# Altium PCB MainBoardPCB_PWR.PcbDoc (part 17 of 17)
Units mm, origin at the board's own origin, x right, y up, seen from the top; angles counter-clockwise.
Board outline 333.63 x 349.38 mm, 16 copper layers (L1, L2 (GND), L3 (Sign), L4 (GND), L5 (Sign), L6 (PWR/GND), L7(PWR/GND), L8 (PWR/GND), L9 (PWR/GND), L10 (PWR/GND), L11 (PWR/GND), L12 (Sign), L13 (GND), L14 (Sign), L15 (GND), L16), stack 2.503 mm thick; 2187 components, 1615 nets, 7987 pads, 1695 vias.
Unrouted connection lines stored in the file: 4757.
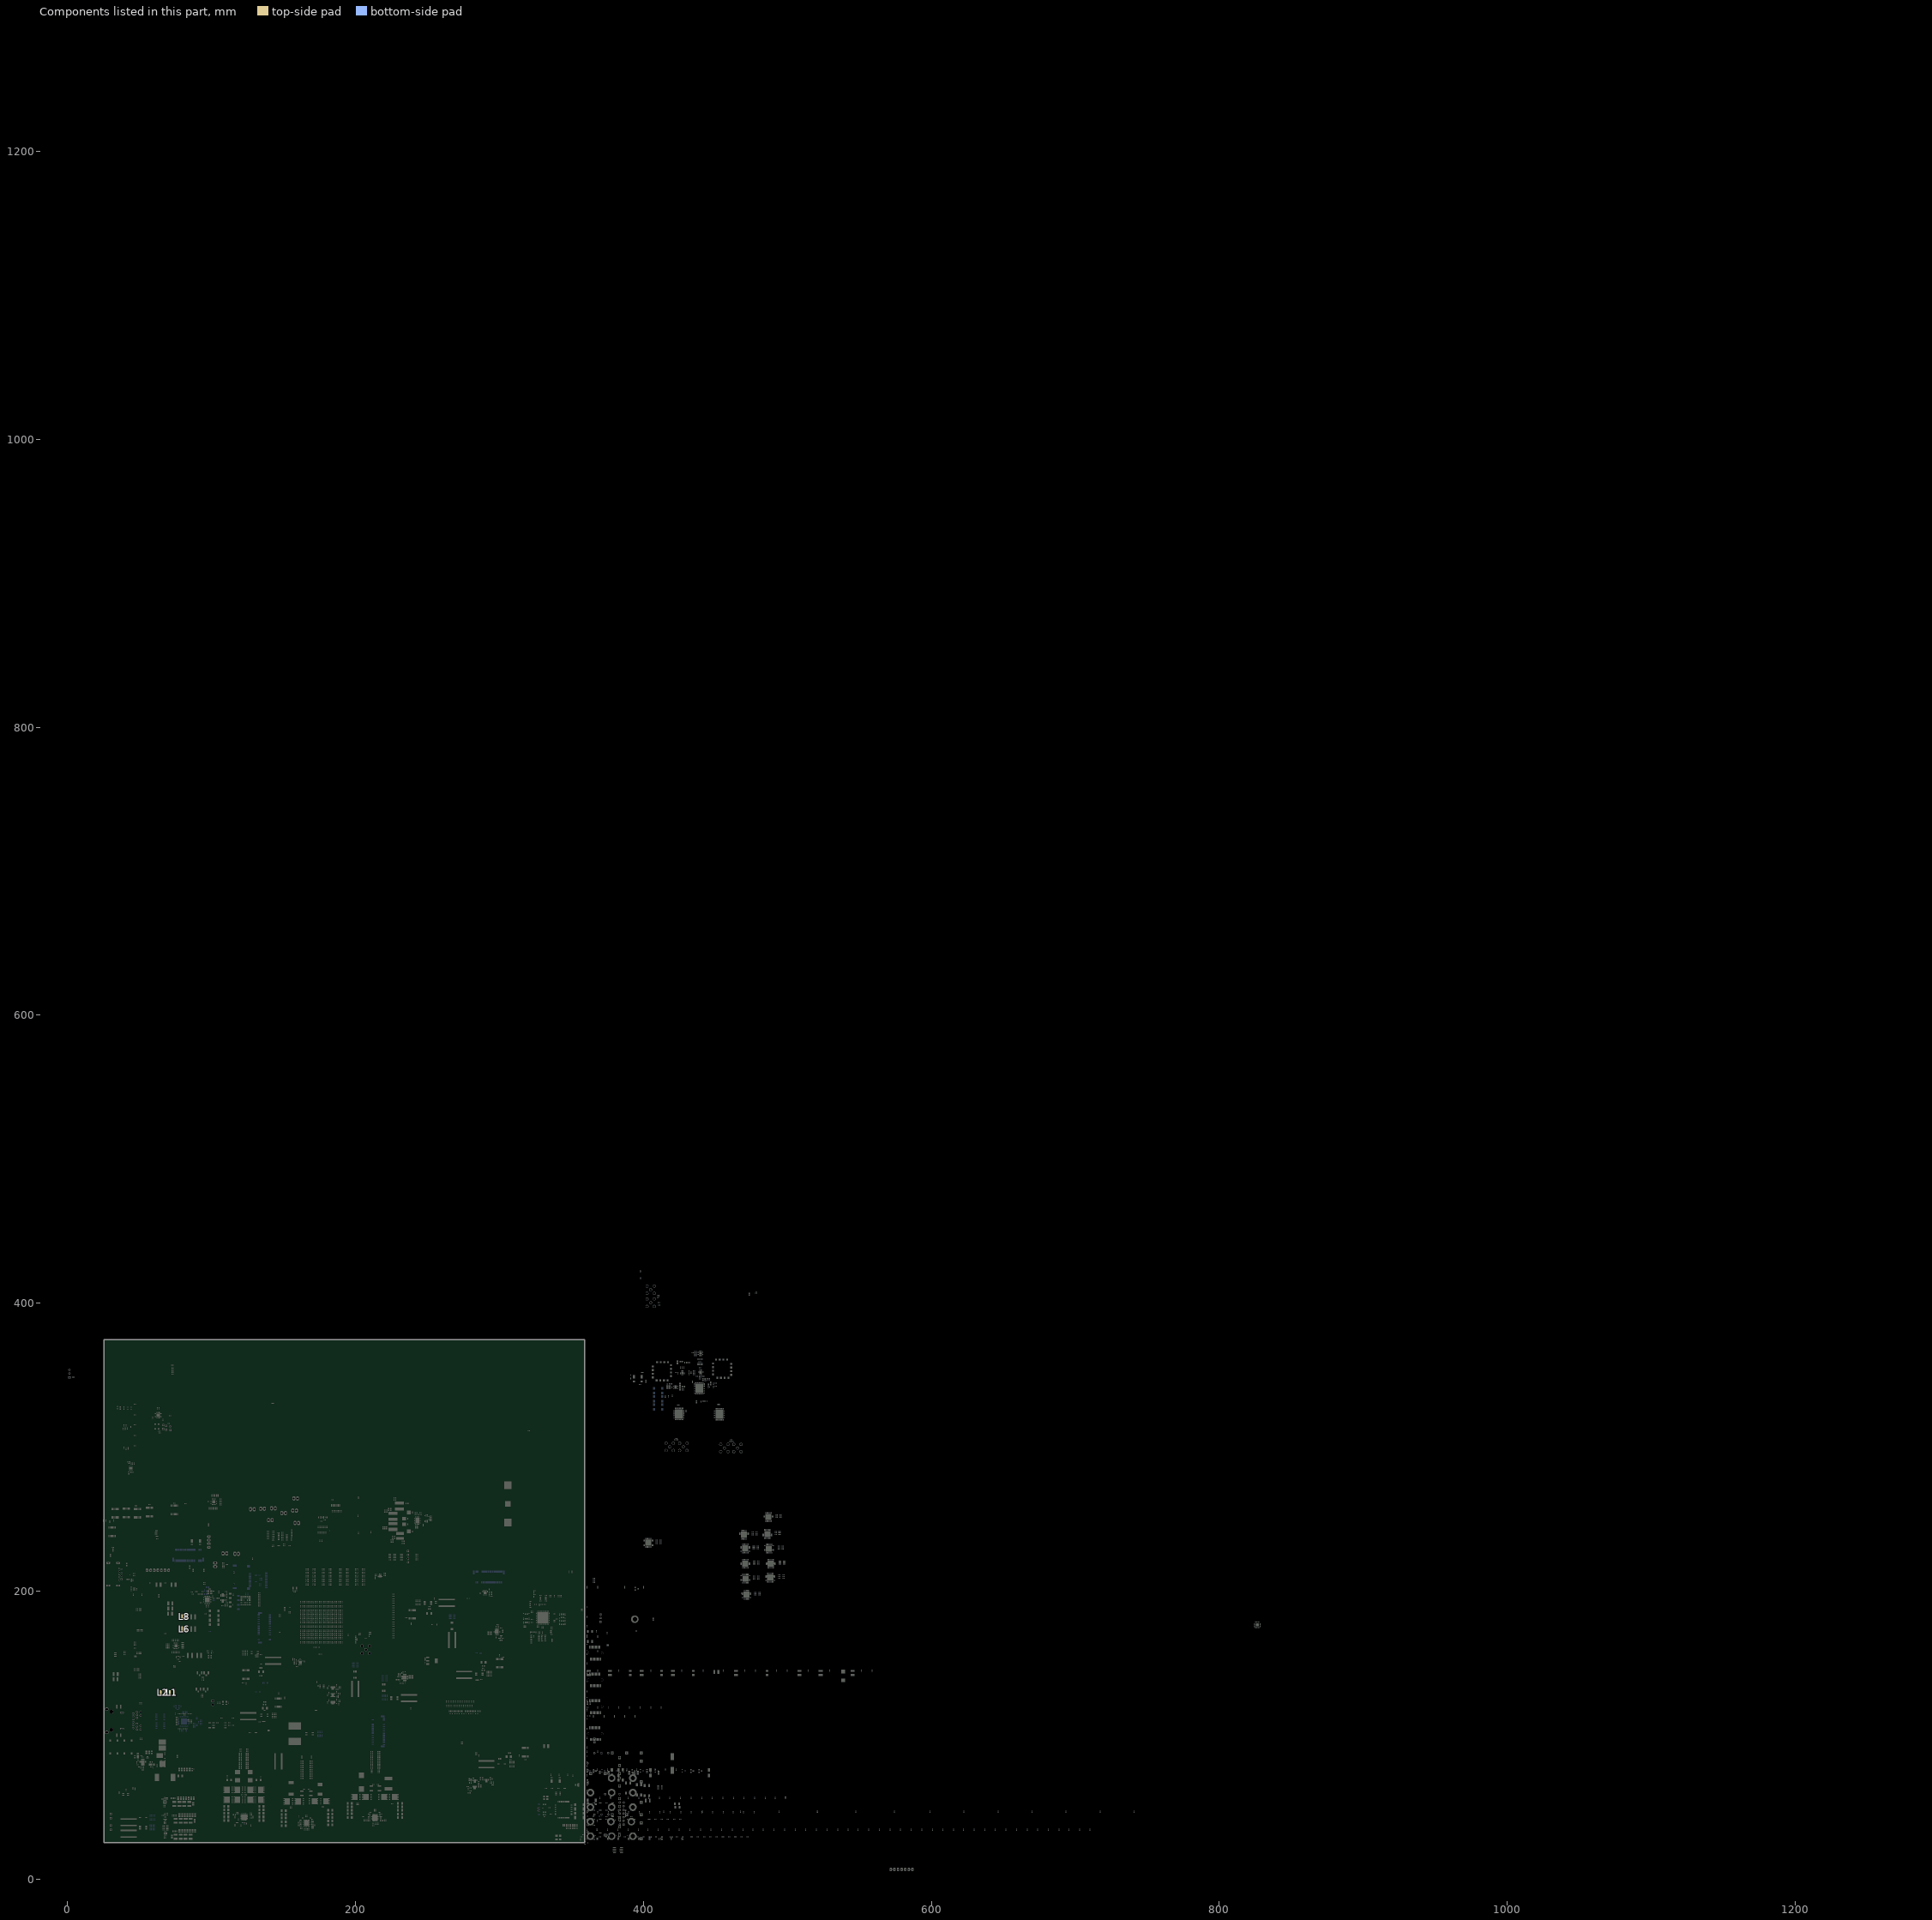
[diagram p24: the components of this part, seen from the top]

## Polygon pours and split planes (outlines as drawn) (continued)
NetD17_2 on L1 "NETD17_2_L01_P076" (solid, remove dead copper, pour order 76): 235.887,250.943 237.571,250.943 238.507,250.007 241.424,250.007 241.424,249.683 240.724,249.683 240.714,249.673 235.887,249.673
NetD18_2 on L1 "NETD18_2_L01_P074" (solid, remove dead copper, pour order 74): 239.187,255.313 239.187,252.923 239.993,252.117 239.993,250.708 241.399,250.708 241.399,251.887 240.724,252.562 240.724,255.313
NetD18_1 on L1 "NETD18_1_L01_P073" (solid, remove dead copper, pour order 73): 234.559,254.669 231.738,254.669 230.427,255.98 230.352,255.98 227.457,255.98 227.457,258.616 235.884,258.616 238.552,255.948 238.552,253.181 239.693,252.04 239.693,250.481 241.377,250.481 241.424,250.433 241.424,250.183 238.912,250.183 235.87,253.225 235.87,253.358
3.3V_Stable_2 on L1 "3.3V_STABLE_2_L01_P068" (solid, remove dead copper, pour order 68): 277.204,59.376 278.954,59.376 278.954,61.24 279.181,61.467 281.697,61.467 281.954,61.725 281.954,63.534 281.879,63.609 279.061,63.609 278.954,63.501 278.954,62.584 277.204,62.584
5V_RAIL on L1 "5V_RAIL_L01_P067" (solid, remove dead copper, pour order 67): 286.481,67.053 286.481,66.157 286.629,66.009 287.736,66.009 287.999,65.746 287.999,64.784 287.899,64.684 284.99,64.684 284.589,64.283 284.589,63.534 283.904,63.534 283.754,63.384 283.754,62.159 283.979,61.934 289.134,61.934 289.134,68.22 289.095,68.259 290.08,68.259 290.131,68.309 290.131,69.809 285.186,69.809 284.832,69.455 284.832,67.984 283.797,67.984 283.797,66.784 284.687,66.784 284.832,66.639 285.072,66.879 285.072,67.053
3.3V_Stable_1 on L1 "3.3V_STABLE_1_L01_P066" (solid, pour order 66): 291.798,69.809 296.994,69.809 296.994,66.96 296.977,66.943 292.766,66.943 292.766,68.909 292.691,68.983 291.822,68.983
Power_3.3_2 on L1 "POWER_3.3_2_L01_P064" (solid, remove dead copper, pour order 64): 227.504,145.003 227.547,144.96 234.325,144.96 234.325,142.049 231.624,139.348 227.504,139.348
3.3V_Stable_3 on L1 "3.3V_STABLE_3_L01_P063" (solid, remove dead copper, pour order 63): 277.738,69.234 279.518,69.234 279.642,69.11 279.642,66.899 277.748,66.899 277.738,66.909 277.738,65.934 281.637,65.934 281.976,66.273 281.976,69.113 282.772,69.909 282.772,70.737 277.738,70.737
FTDI_GND on L1 "FTDI_GND_L01_P062" (solid, remove dead copper, pour order 62): 41.035,290.882 41.074,290.843 47.216,290.843 47.216,288.889 47.216,282.109 44.836,282.109 43.388,280.661 41.014,280.661
FTDI_VccIO on L1 "FTDI_VCCIO_L01_P060" (solid, remove dead copper, pour order 60): 42.576,286.185 42.745,286.354 42.745,290.799 42.798,290.851 47.223,290.851 47.223,288.898 46.967,288.642 44.826,288.642 44.826,287.89 43.276,286.34
FTDI_5V on L1 "FTDI_5V_L01_P059" (solid, remove dead copper, pour order 59): 42.145,284.34 42.145,282.268 44.576,282.268 44.576,284.34 42.254,284.34
1V8@0.5A_ADC_filtered on L1 "1V8@0.5A_ADC_FILTERED_L01_P058" (solid, remove dead copper, pour order 58): 299.809,172.083 299.857,172.131 299.857,173.561 300.043,173.747 300.877,173.747 301.054,173.925 301.054,175.978 300.887,176.145 298.859,176.145 298.709,176.295 298.709,177.348 298.738,177.377 302.695,177.377 304.046,176.025 304.046,172.155 301.827,172.155 301.755,172.083
0V9@1A_REG3 on L1 "0V9@1A_REG3_L01_P057" (solid, remove dead copper, pour order 57): 299.809,171.363 299.817,171.355 301.313,171.355 301.313,168.586 301.053,168.326 301.053,165.034 300.877,164.858 299.915,164.858 299.67,165.103 299.67,166.403 300.104,166.837 300.104,167.468 299.609,167.963 299.609,171.368
ANGD on L1 "ANGD_L01_P055" (solid, remove dead copper, pour order 55): 115.642,37.426 115.589,37.479 115.589,48.586 130.338,48.586 130.34,48.588 130.34,37.426
AGND_2 on L1 "AGND_2_L01_P053" (solid, remove dead copper, pour order 53): 157.199,33.778 157.199,43.499 173.008,43.499 173.008,34.274 171.996,33.262 157.715,33.262
Vout_5V@10A_INA on L1 "VOUT_5V@10A_INA_L01_P049" (solid, remove dead copper, pour order 49): 169.482,63.617 179.17,63.617 179.141,63.646 179.141,89.957 169.468,89.957
Vout1_2 on L1 "VOUT1_2_L01_P048" (solid, remove dead copper, pour order 48): 152.928,69.366 152.928,71.725 ccw(c152.251,71.725) 152.251,72.402 150.843,72.402 cw(c150.843,74.942) 148.303,74.942 148.303,87.517 cw(c150.833,87.517) 150.833,90.047 162.59,90.047 162.59,63.626 162.618,63.597 152.931,63.597
NetC646_2 on L1 "NETC646_2_L01_P045" (solid, remove dead copper, pour order 45): 167.705,60.63 167.686,60.63 167.686,62.708 170.355,62.708 170.355,60.583 167.705,60.583
NetC645_2 on L1 "NETC645_2_L01_P044" (solid, remove dead copper, pour order 44): 161.498,60.63 161.48,60.63 161.48,62.707 164.148,62.707 164.148,60.582 161.498,60.582
NetC568_2 on L1 "NETC568_2_L01_P043" (solid, remove dead copper, pour order 43): 290.07,201.499 292.217,201.499 292.535,201.182 293.335,201.182 293.335,200.21 293.735,199.81 295.235,199.81 295.235,198.46 293.735,198.46 293.735,198.932 293.635,199.031 292.535,199.031 292.535,198.684 292.19,198.339 292.186,198.343 291.09,198.343 291.09,200.081 291.06,200.111 290.07,200.111
ADP1741_3.6V on L1 "ADP1741_3.6V_L01_P042" (solid, remove dead copper, pour order 42): 286.064,198.557 287.63,198.557 287.98,198.206 288.8,198.206 288.99,198.396 288.99,200.081 290.04,200.081 290.07,200.111 290.07,201.499 286.064,201.499
Vout_1_Selector on L1 "VOUT_1_SELECTOR_L01_P041" (solid, remove dead copper, pour order 41): 71.506,50.342 73.252,52.088 74.649,52.088 74.799,52.238 89.845,52.238 89.845,54.95 88.723,56.072 71.493,56.072 68.767,53.347 66.181,53.347 66.181,52.852 69.112,52.895 69.112,52.594 68.967,50.188 68.921,50.086 64.58,45.745 64.58,42.155 67.81,42.155 67.81,42.7 67.66,42.85 66.66,42.845 66.66,43.65 66.181,44.13 66.181,44.75 66.406,44.75 71.493,50.336 71.506,50.324
Battery_PWR on L1 "BATTERY_PWR_L01_P037" (solid, remove dead copper, pour order 37): 68.017,31.762 70.729,31.762 70.729,36.509 70.621,36.617 69.303,36.617 69.303,32.717 69.167,32.582 68.017,32.582
AGND_1 on L1 "AGND_1_L01_P036" (solid, remove dead copper, pour order 36): 205.386,36.611 205.386,45.614 205.745,45.973 221.555,45.973 221.555,36.748 220.984,36.177 205.82,36.177
NetC638_2 on L1 "NETC638_2_L01_P029" (solid, remove dead copper, pour order 29): 215.592,63.946 215.573,63.946 215.573,66.023 218.242,66.023 218.242,63.898 215.592,63.898
NetC637_2 on L1 "NETC637_2_L01_P028" (solid, remove dead copper, pour order 28): 209.72,63.946 209.701,63.946 209.701,66.023 212.37,66.023 212.37,63.898 209.72,63.898
5V_LN on L1 "5V_LN_L01_P022" (solid, remove dead copper, pour order 22): 424.658,343.392 427.76,343.392 427.76,341.142 426.158,341.142 426.158,341.942 424.37,341.942 424.37,342.042 423.155,342.042 423.155,343.392 423.146,343.392
3V3_Rail on L1 "3V3_RAIL_L01_P020" (solid, pour order 20): 291.419,173.273 296.753,173.273 296.753,171.908 296.709,171.863 295.859,171.863 295.859,171.583 296.709,171.583 296.709,170.373 295.595,170.373 295.235,170.733 291.359,170.733 291.349,170.723
PGND on L1 "PGND_L01_P017" (solid, pour order 17): 53.182,82.572 53.182,84.012 54.121,84.951 55.425,84.951 55.425,85.236 56.031,85.842 60.425,85.842 60.881,85.387 60.881,83.335 61.435,82.78 63.03,82.78 63.03,78.798 62.832,78.6 61.725,78.6 60.695,79.629 60.695,80.69 58.401,80.69 58.366,80.655 58.262,80.76 58.262,82.063 57.753,82.572
PGND on L1 "PGND_L01_P015" (solid, remove dead copper, pour order 15): 43.053,88.444 42.903,88.294 37.586,88.294 37.586,86.446 36.583,85.444 32.846,85.444 32.846,90.786 34.583,92.523 72.408,92.523 73.958,90.972 73.958,81.438 86.353,81.438 88.128,79.663 88.128,76.18 72.825,76.18 72.713,76.069 69.447,79.335 69.447,88.717 61.746,88.717 61.185,88.157 47.908,88.157 47.135,87.384 47.135,85.239 42.848,85.239 43.053,85.444
CSP on L1 "CSP_L01_P013" (solid, pour order 13): 71.099,73.536 76.498,73.536 76.498,70.052 74.498,68.052 71.099,68.052
VCCINT on L1 "VCCINT_L01_P012" (solid, remove dead copper, pour order 12): 53.697,82.057 58.157,82.057 58.366,81.848 58.366,80.655 59.054,80.655 59.189,80.52 59.189,78.59 56.386,78.59 56.178,78.798 56.178,80.857 56.069,80.857 55.54,81.386 55.511,81.357 53.697,81.357
Ground_PWR_PoE on L1 "GROUND_PWR_POE_L01_P011" (solid, remove dead copper, pour order 11): 47.633,86.427 51.357,86.427 51.357,85.014 50.944,84.601 50.944,83.691 49.689,82.436 46.798,82.436 46.398,82.036 46.398,80.055 48.424,80.055 48.66,79.82 48.66,77.599 48.816,77.442 53.697,77.442 53.697,76.545 53.447,76.295 47.788,76.295 44.998,79.085 44.998,84.69 45.322,85.014 47.633,85.014
V_PoE+ on L1 "V_POE+_L01_P010" (solid, remove dead copper, pour order 10): 47.768,86.642 52.167,86.642 52.182,86.627 52.182,82.572 52.482,82.572 52.532,82.622 52.532,83.83 52.999,83.83 53.697,84.527 53.697,86.127 60.595,86.127 61.166,85.557 61.166,83.697 62.169,83.697 62.441,83.968 66.172,83.968 66.172,83.993 66.38,84.202 66.38,87.502 61.88,87.502 61.365,88.017 47.768,88.017 47.768,87.029
NetC693_1 on L1 "NETC693_1_L01_P009" (solid, pour order 9): 66.98,87.172 66.982,87.173 69.088,87.173 69.088,76.953 65.672,73.536 65.672,67.995 64.58,66.904 58.928,66.904 58.378,67.454 58.378,77.034 58.928,77.584 63.1,77.584 63.416,77.901 63.416,83.394 63.718,83.697 66.366,83.697 66.616,83.947 66.616,87.129 66.659,87.172 66.98,87.172
NetC581_2 on L1 "NETC581_2_L01_P008" (solid, pour order 8): 416.436,344.927 416.436,343.042 415.636,343.042 415.636,341.692 421.451,341.692 421.505,341.637 421.505,343.032 420.402,343.032 420.257,343.177 418.907,343.177 418.907,344.908 418.889,344.927
0.85V@40A_INA on L1 "0.85V@40A_INA_L01_P007" (solid, pour order 7): 132.007,71.916 124.577,71.916 124.577,75.386 125.138,75.946 125.138,91.327 119.903,91.327 119.903,75.851 120.46,75.294 120.46,71.916 112.916,71.916 112.916,95.221 132.007,95.221
no net on L1 "NONET_L01_P006" (solid, pour order 6): 132.074,71.89
FTDI_GND on L2 (GND) "FTDI_GND_L02_P061" (solid, remove dead copper, pour order 61): 41.042,290.89 41.081,290.851 47.223,290.851 47.223,288.898 47.223,282.118 44.843,282.118 43.395,280.67 41.021,280.67
ANGD on L2 (GND) "ANGD_L02_P056" (solid, remove dead copper, pour order 56): 115.642,37.426 115.589,37.479 115.589,48.586 130.338,48.586 130.34,48.588 130.34,37.426
AGND_2 on L2 (GND) "AGND_2_L02_P054" (solid, remove dead copper, pour order 54): 157.199,33.778 157.199,43.499 173.008,43.499 173.008,34.274 171.996,33.262 157.714,33.262
AGND_1 on L2 (GND) "AGND_1_L02_P035" (solid, remove dead copper, pour order 35): 205.386,45.614 205.745,45.973 221.555,45.973 221.555,36.748 220.984,36.177 205.82,36.177 205.386,36.611
PGND on L2 (GND) "PGND_L02_P019" (solid, remove dead copper, pour order 19): 43.053,88.444 42.903,88.294 37.586,88.294 37.586,86.446 36.583,85.444 32.846,85.444 32.846,90.786 34.583,92.523 34.633,92.472 45.546,92.472 72.421,92.472 73.958,90.935 73.958,81.438 86.353,81.438 88.128,79.663 88.128,76.18 72.825,76.18 72.713,76.069 69.447,79.335 69.447,88.017 69.424,87.994 47.745,87.994 47.135,87.384 47.135,85.239 43.014,85.239 43.053,85.444 43.053,85.601
Ground_PWR_PoE on L2 (GND) "GROUND_PWR_POE_L02_P014" (solid, remove dead copper, pour order 14): 51.357,86.427 51.182,86.252 51.182,82.572 53.482,82.572 53.697,82.357 53.697,76.545 53.447,76.295 47.788,76.295 44.998,79.085 44.998,84.69 45.322,85.014 47.633,85.014 47.633,86.427
V_PoE+ on L8 (PWR/GND) "V_POE+_L08_P100" (solid, remove dead copper, pour order 100): 32.733,92.498 30.373,92.498 ccw(c30.373,89.958) 27.833,89.958 27.833,84.976 ccw(c30.373,84.976) 30.373,82.436 64.243,82.436 ccw(c64.243,84.573) 66.38,84.573 66.38,86.93 ccw(c65.016,86.93) 65.016,88.294 47.934,88.294 cw(c47.934,88.944) 47.284,88.944 47.284,89.983 ccw(c44.744,89.983) 44.744,92.523 32.733,92.523
PWR_OUT_20V on L6 (PWR/GND) "PWR_OUT_20V_L06_P108" (solid, remove dead copper, pour order 108): 66.817,31.612 cw(c66.817,33.433) 65.529,32.145 65.133,32.542 63.463,32.542 ccw(c63.463,31.444) 62.687,32.22 ccw(c63.178,31.73) 62.484,31.73 62.484,29.493 ccw(c63.351,29.493) 62.738,28.88 64.259,27.359 ccw(c66.055,29.155) 66.055,26.615 109.903,26.615 ccw(c109.903,29.155) 111.699,27.359 112.8,28.46 ccw(c111.501,29.76) 113.338,29.76 113.338,36.425 112.023,37.74 ccw(c110.227,35.944) 110.227,38.484 97.181,38.484 ccw(c97.181,36.148) 95.529,37.8 93.896,36.166 cw(c92.099,37.962) 92.099,35.422 74.646,35.422 ccw(c74.646,32.882) 72.85,34.678 70.528,32.356 cw(c68.732,34.152) 68.732,31.612
eMMC_VccQ on L6 (PWR/GND) "EMMC_VCCQ_L06_P114" (solid, remove dead copper, pour order 114): 114.036,190.759 cw(c114.036,190.561) 114.234,190.561 ccw(c114.316,190.561) 114.316,190.479 116.002,190.479 ccw(c116.002,190.855) 116.378,190.855 cw(c116.868,190.855) 116.868,191.344 119.22,191.344 cw(c119.22,190.694) 119.87,190.694 119.87,190.089 cw(c118.775,190.089) 118.775,188.994 117.554,188.994 ccw(c117.554,188.409) 116.968,188.409 cw(c116.754,188.409) 116.754,188.194 111.457,188.194 cw(c111.457,189.309) 110.343,189.309 110.343,190.863 cw(c110.557,190.863) 110.557,191.077 ccw(c110.557,191.212) 110.692,191.212 110.692,194.5 cw(c110.84,194.5) 110.84,194.647 111.65,194.647 cw(c111.65,194.114) 112.184,194.114 112.184,191.329 ccw(c112.754,191.329) 112.754,190.759
Vout_2_Selector on L6 (PWR/GND) "VOUT_2_SELECTOR_L06_P107" (solid, pour order 107): 66.61,41.85 65.732,41.85 ccw(c65.736,40.768) 64.968,41.53 ccw(c65.432,41.15) 64.832,41.15 64.832,32.011 ccw(c65.338,32.517) 65.338,31.801 67.6,31.801 ccw(c67.6,32.178) 67.867,31.912 67.939,31.984 ccw(c67.752,32.172) 68.017,32.172 68.017,32.912 cw(c68.871,32.912) 68.267,33.515 ccw(c67.879,33.904) 68.428,33.904 68.428,38.675 cw(c70.968,38.675) 69.172,40.471 69.255,40.555 89.275,40.555 ccw(c89.275,41.713) 90.094,40.894 90.094,43.488 ccw(c89.245,43.488) 89.845,44.088 ccw(c89.427,43.67) 89.427,44.261 77.066,44.261 ccw(c77.066,43.896) 76.807,44.154 cw(c76.53,44.432) 76.53,44.039 72.492,44.039 ccw(c72.492,41.499) 70.696,43.295 69.419,42.019 cw(c69.01,42.428) 69.01,41.85
Vout_1_Selector on L6 (PWR/GND) "VOUT_1_SELECTOR_L06_P104" (solid, remove dead copper, pour order 104): 66.473,42.136 65.568,42.136 cw(c65.568,44.676) 63.772,42.88 63.737,42.915 cw(c64.416,43.156) 63.695,43.156 63.695,52.595 cw(c64.395,52.595) 64.395,53.295 68.829,53.295 ccw(c68.829,53.601) 69.046,53.385 70.898,55.238 cw(c70.926,55.21) 70.926,55.249 71.56,55.883 cw(c71.883,55.561) 71.883,56.017 87.648,56.017 ccw(c87.648,56.053) 87.673,56.028 88.541,56.028 cw(c88.541,55.405) 88.982,55.845 89.353,55.473 cw(c88.176,54.295) 89.841,54.295 89.841,52.852 cw(c88.359,54.335) 88.359,52.238 74.395,52.238 ccw(c74.395,49.698) 72.599,51.494 67.206,46.101 ccw(c68.958,44.35) 66.48,44.35 66.48,44.084 ccw(c67.095,44.084) 66.66,43.65 ccw(c67.143,44.132) 67.143,43.45 67.198,43.45 cw(c67.198,42.938) 67.56,43.3 cw(c66.961,42.698) 67.81,42.7 cw(c67.013,42.7) 67.577,42.136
